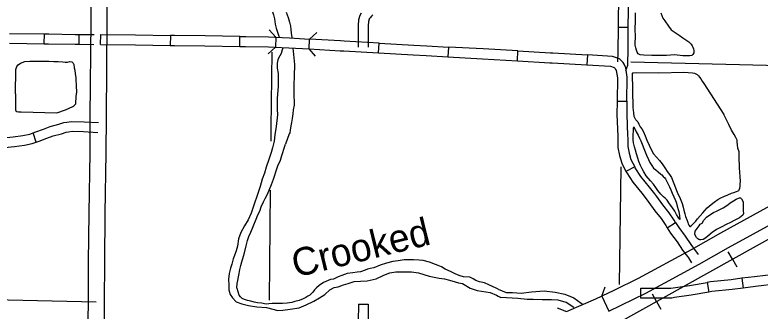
# Model space of a CAD drawing. Extents: x 1196286 to 1268366, y 2040822 to 2082115.
# Drawn here: x 1227299 to 1231542, y 2058115 to 2059803 of the extents above; entities that cross this region are included whole.
import ezdxf

# ---------------------------------------------------------------- set-up
doc = ezdxf.new("R2010")
doc.units = 0
for name, color, linetype in [('60', 7, 'Continuous'), ('61', 7, 'Continuous'), ('62', 7, 'Continuous'), ('G-ANNO-SYMB', 7, 'Continuous'), ('Level 69', 7, 'Continuous'), ('Level 71', 7, 'Continuous'), ('Level 72', 7, 'Continuous'), ('Level 76', 7, 'Continuous'), ('Level 81', 7, 'Continuous'), ('Level 83', 7, 'Continuous'), ('Level 84', 7, 'Continuous'), ('Level 87', 7, 'Continuous')]:
    doc.layers.add(name, color=color, linetype=linetype)

msp = doc.modelspace()

# ---------------------------------------------------------------- linework, layer by layer
at = {"layer": '60'}
for points in [[(1228761.5, 2059591.7), (1228756.7, 2059158.4)], [(1233094.3, 2059466.8), (1232738.1, 2059486.8), (1230806.4, 2059534.5)], [(1228756.7, 2059158.4), (1228756, 2059084.4)], [(1230749.7, 2058938.2), (1230739.2, 2058266.7)], [(1228753.1, 2058804.5), (1228746.7, 2058177.5)]]:
    msp.add_lwpolyline(points, dxfattribs=at)
at = {"layer": '61'}
for p, q in [((1227466.4, 2059638.8), (1227467.2, 2059695)), ((1230733.3, 2059733.9), (1230789.6, 2059733.2)), ((1227664.4, 2059635.9), (1227665.2, 2059692.2)), ((1231438.6, 2058302), (1231446, 2058246.2)), ((1231241, 2058278.9), (1231250.4, 2058223.4)), ((1230862.3, 2058189.6), (1230862.2, 2058245.9)), ((1229254.9, 2058155.2), (1229311.1, 2058154.3))]:
    msp.add_line(p, q, dxfattribs=at)
for points in [[(1230735.7, 2059931.9), (1230733.3, 2059733.9)], [(1230792, 2059931.2), (1230789.6, 2059733.2)], [(1227269.3, 2059697.9), (1227467.2, 2059695)], [(1227467.2, 2059695), (1227491.7, 2059694.7), (1227642.6, 2059692.5), (1227665.2, 2059692.2)], [(1230733.3, 2059733.9), (1230731.6, 2059595.4), (1230730.8, 2059535.9)], [(1230789.6, 2059733.2), (1230787.9, 2059594.6), (1230787.1, 2059535.2)], [(1227665.2, 2059692.2), (1227750.3, 2059691)], [(1227268.5, 2059641.6), (1227466.4, 2059638.8)], [(1227466.4, 2059638.8), (1227490.8, 2059638.4), (1227641.8, 2059636.3), (1227664.4, 2059635.9)], [(1227664.4, 2059635.9), (1227749.5, 2059634.7)], [(1230787.1, 2059535.2), (1230786.8, 2059514.3), (1230776.1, 2059484.6)], [(1231438.6, 2058302), (1231376.2, 2058293.7), (1231259.8, 2058282.1), (1231241, 2058278.9)], [(1231635.6, 2058326.2), (1231509.2, 2058311.4), (1231438.6, 2058302)], [(1231046, 2058247.7), (1231139.8, 2058261.8), (1231241, 2058278.9)], [(1231642.1, 2058270.4), (1231516.2, 2058255.5), (1231446, 2058246.2)], [(1230862.2, 2058245.9), (1231034.4, 2058246), (1231046, 2058247.7)], [(1231250.4, 2058223.4), (1231148.6, 2058206.3), (1231054.4, 2058192.1)], [(1231446, 2058246.2), (1231382.7, 2058237.8), (1231267.3, 2058226.3), (1231250.4, 2058223.4)], [(1231054.4, 2058192.1), (1231038.6, 2058189.7), (1230862.3, 2058189.6)], [(1229254.9, 2058155.2), (1229251.6, 2057957.3)], [(1229311.1, 2058154.3), (1229307.8, 2057956.3)]]:
    msp.add_lwpolyline(points, dxfattribs=at)
at = {"layer": '62'}
for points in [[(1228766.8, 2059820.7), (1228771.5, 2059802.9), (1228777.9, 2059780.8), (1228780.7, 2059750.7), (1228786.7, 2059727.9), (1228798.4, 2059692.9), (1228802.1, 2059681.9), (1228803.3, 2059678.4)], [(1228844.3, 2059818.9), (1228855.3, 2059789.3), (1228863.1, 2059761.2), (1228867.6, 2059739.6), (1228870.7, 2059719.9), (1228872.3, 2059699.6), (1228876.3, 2059674.7)], [(1230977.2, 2059814.8), (1230987.1, 2059784.8), (1230999, 2059769.7), (1231019.4, 2059739.7), (1231036, 2059718.1), (1231036.3, 2059718.5), (1231081.1, 2059687.7), (1231102.3, 2059673.5), (1231119.9, 2059660.5), (1231136, 2059649.5), (1231144, 2059641.7), (1231149.1, 2059635.9), (1231154.8, 2059626.7), (1231157.9, 2059618.7), (1231162.5, 2059609.5), (1231164.8, 2059598.9), (1231165, 2059593.2), (1231164, 2059587.6), (1231158.8, 2059577.3), (1231152.7, 2059572.2), (1231141.8, 2059570.3), (1231123, 2059569.4), (1231101.3, 2059570.1), (1231054.3, 2059575.4), (1231009.6, 2059572.3), (1230963.9, 2059572.3), (1230925.3, 2059572), (1230880.8, 2059573.1), (1230859.5, 2059576.4), (1230851, 2059578.9), (1230848.1, 2059581.3), (1230841.6, 2059590.5), (1230839, 2059601.5), (1230833.8, 2059616.3), (1230831.3, 2059631.5), (1230831.2, 2059650.3), (1230831.8, 2059670.9), (1230831.7, 2059689), (1230829.9, 2059713), (1230833, 2059779.3)], [(1230833, 2059779.3), (1230832.3, 2059814.6)], [(1228824.1, 2059614.2), (1228821.8, 2059604.6), (1228815.9, 2059584.1), (1228808.3, 2059569.6), (1228799.7, 2059557.1), (1228795.6, 2059548.2), (1228791.6, 2059528.1), (1228793.3, 2059499), (1228797.2, 2059468.8), (1228798.5, 2059437.2), (1228798.3, 2059397.3), (1228792.8, 2059327.6), (1228792.3, 2059267), (1228794.2, 2059233.9)], [(1228882.5, 2059611.4), (1228882.9, 2059595.8), (1228890.6, 2059520), (1228888.5, 2059453.8), (1228887, 2059405), (1228886.4, 2059375.3), (1228887.6, 2059353.1), (1228887, 2059335.8), (1228889.3, 2059313.5), (1228888.6, 2059289.1), (1228883.9, 2059261.4), (1228882.5, 2059240.1), (1228877.9, 2059212), (1228873.4, 2059190.3), (1228870.6, 2059171.2), (1228867.2, 2059147.3), (1228864.8, 2059131.9), (1228860.2, 2059125.7), (1228839.4, 2059067)], [(1227303, 2059353), (1227304.2, 2059492), (1227310, 2059508.7), (1227318.9, 2059519.7), (1227331.2, 2059528.3), (1227355.5, 2059537.7), (1227385.1, 2059539), (1227438.7, 2059539.5), (1227467.9, 2059540.4), (1227491.9, 2059540.1), (1227520.7, 2059538.7), (1227546.1, 2059538.3), (1227572.6, 2059535.9), (1227585.3, 2059534.4), (1227598.1, 2059534.4), (1227611.3, 2059537.3), (1227623.6, 2059535.8), (1227631.2, 2059528), (1227634.3, 2059520.8), (1227637.5, 2059502.3), (1227639.7, 2059489), (1227642.4, 2059468.3), (1227645.5, 2059447.1), (1227647.2, 2059432), (1227647.5, 2059405.3), (1227649.6, 2059357.6)], [(1230833.5, 2059205.6), (1230825.6, 2059224), (1230822, 2059244.4), (1230819, 2059275.8), (1230816, 2059471.6), (1230816.3, 2059473.6), (1230821.3, 2059473.8), (1230840.6, 2059475.4), (1230965.5, 2059473.3), (1231106.7, 2059476.9), (1231156, 2059473.2), (1231167.7, 2059470.4), (1231175.7, 2059467), (1231184.4, 2059463), (1231191.2, 2059456.8), (1231197.7, 2059448.9), (1231203.5, 2059439.9), (1231212.5, 2059425.5), (1231221.2, 2059412.7), (1231297.5, 2059295.2), (1231336.2, 2059236.3)], [(1227303, 2059353), (1227302.5, 2059262.4), (1227305.1, 2059255.9), (1227311, 2059252.8), (1227319.6, 2059251.6), (1227334.6, 2059250.3), (1227537.9, 2059245.6), (1227587.2, 2059261.4), (1227629.4, 2059280.4), (1227635.8, 2059284.4), (1227641.5, 2059290), (1227645.4, 2059296.7), (1227646.3, 2059306.1), (1227649.6, 2059357.6)], [(1228794.2, 2059233.9), (1228787.7, 2059167.8), (1228779.8, 2059119.7), (1228776.3, 2059082.9), (1228766.5, 2059046.5), (1228758.6, 2059019.2), (1228744.6, 2058978.8), (1228729.4, 2058935.4), (1228719.5, 2058900.9), (1228707.8, 2058867.2), (1228696.4, 2058825.6), (1228682.4, 2058785.2), (1228657.4, 2058713.7), (1228643.8, 2058673.7), (1228626.8, 2058636), (1228606.9, 2058602), (1228586.1, 2058563.2), (1228572.9, 2058528), (1228566.7, 2058485.6), (1228559.6, 2058458.6), (1228549.9, 2058432.8), (1228542.5, 2058412.2), (1228534.6, 2058383.4), (1228527.5, 2058359.8), (1228519.3, 2058329.8), (1228514.7, 2058297.2), (1228516.5, 2058263.3), (1228516.5, 2058237), (1228525.5, 2058209.4), (1228538.4, 2058190.4), (1228559.4, 2058168.3), (1228592.2, 2058156.6), (1228628.8, 2058146.3), (1228677, 2058138.9), (1228730.9, 2058135.1), (1228795.8, 2058118), (1228825.1, 2058121.4), (1228867.1, 2058126.1), (1228917.4, 2058133.3), (1228958.1, 2058150.4), (1229000.4, 2058172.7), (1229033.2, 2058190.3), (1229063.4, 2058209.9), (1229092.6, 2058236.1), (1229116.8, 2058249.3), (1229140.1, 2058254.3), (1229169.4, 2058264), (1229197.3, 2058273.1), (1229230.7, 2058283.1), (1229266.7, 2058284.9), (1229305, 2058287.4), (1229356.4, 2058299.8), (1229399.8, 2058319.1), (1229434.4, 2058332.9), (1229468.2, 2058338.5), (1229509.8, 2058339.4), (1229556.6, 2058339.1), (1229596.6, 2058333), (1229626.8, 2058324.6), (1229658.2, 2058314.8), (1229685.4, 2058308), (1229715, 2058302.7), (1229744.9, 2058299.3), (1229774.4, 2058290.6), (1229805.7, 2058281.2), (1229825.1, 2058276), (1229847.9, 2058271.9), (1229890.6, 2058245.4), (1229930.1, 2058232.1), (1229981.3, 2058224.2), (1230004.9, 2058220.5), (1230041.8, 2058205.3), (1230050.7, 2058199.9), (1230066, 2058192.5)], [(1230833.5, 2059205.6), (1230845.8, 2059193.7), (1230851.4, 2059181.3), (1230859.8, 2059165.8), (1230868.1, 2059154.3), (1230877.7, 2059137.8), (1230888.2, 2059113.5), (1230897.6, 2059089.2), (1230909.7, 2059060.8), (1230922.8, 2059032.8), (1230935.5, 2059012.3), (1230951.7, 2058993.4), (1230968.6, 2058973.7), (1230984.1, 2058954), (1231002.7, 2058926.6), (1231013.2, 2058910.3), (1231026.4, 2058894), (1231036.9, 2058876.2), (1231059.2, 2058818.5), (1231069.8, 2058793.4), (1231086.6, 2058757.4), (1231098.6, 2058727.9), (1231104, 2058707.2), (1231107.6, 2058691.1), (1231112.8, 2058669), (1231116.7, 2058655), (1231125.8, 2058631.7), (1231129.7, 2058621.1), (1231132.5, 2058611.7), (1231135.5, 2058605.8), (1231140.8, 2058597.5), (1231141.2, 2058597), (1231141.7, 2058596.9), (1231143.1, 2058597.3), (1231149.3, 2058601.9), (1231155.5, 2058607.6), (1231165.6, 2058618.2), (1231175.1, 2058628.1), (1231186.2, 2058641.1), (1231201.3, 2058658.6), (1231216.4, 2058674.7), (1231226.4, 2058688.1), (1231240.7, 2058704.6), (1231262.5, 2058722.7), (1231279.9, 2058736.2), (1231301.2, 2058750.8), (1231317.4, 2058761.2), (1231334.9, 2058768.6), (1231357.2, 2058777.4), (1231378.7, 2058786.4), (1231391.9, 2058792), (1231407.3, 2058797.7), (1231416.9, 2058801), (1231420.2, 2058803.4), (1231422.3, 2058806.3), (1231425.7, 2058815.4), (1231427.8, 2058824.5), (1231428.6, 2058838.4), (1231429.6, 2058856.1), (1231424.3, 2058931.4), (1231421.7, 2058993.6), (1231421.8, 2059022.4), (1231414.7, 2059043.7), (1231412.2, 2059063.1), (1231411.7, 2059079.5), (1231410.3, 2059090.3), (1231403.8, 2059104.7), (1231393.6, 2059121.6), (1231379.4, 2059146.9), (1231363.3, 2059177.9), (1231336.2, 2059236.3)], [(1231083.9, 2058637.3), (1231075.7, 2058650.5), (1231065.9, 2058666.7), (1231055.9, 2058683.9), (1231038.4, 2058708.9), (1231026.7, 2058726.3), (1231012, 2058747.8), (1231000.9, 2058759.2), (1230991.6, 2058767.3), (1230976.2, 2058782.4), (1230960.5, 2058801.9), (1230948.5, 2058819.6), (1230934.6, 2058839), (1230918.2, 2058857.9), (1230893.5, 2058886.7), (1230880, 2058908.3), (1230870.3, 2058926.2), (1230860.7, 2058945.1), (1230851.5, 2058968.7), (1230845.5, 2058987.3), (1230838.4, 2059011), (1230831.5, 2059032.1), (1230825.9, 2059051.8), (1230821.1, 2059074.2), (1230818.5, 2059091.6), (1230818.3, 2059102.2), (1230820, 2059121.1), (1230821, 2059140.2), (1230821.3, 2059156.6), (1230822, 2059166), (1230823.4, 2059162.6), (1230830.1, 2059149.9), (1230836.7, 2059136.9), (1230842.2, 2059127.1), (1230846.9, 2059117.7), (1230855.6, 2059101.6), (1230862.7, 2059085.8), (1230870.2, 2059066.3), (1230880, 2059041.2), (1230895.7, 2059004.8), (1230906.2, 2058979.7), (1230914.1, 2058962.2), (1230924.5, 2058945), (1230935.6, 2058930.7), (1230948.3, 2058919.6), (1230960.8, 2058908.3), (1230976.6, 2058896.5), (1230982, 2058891.3), (1230989.4, 2058883.2), (1230998.5, 2058874.6), (1231003.7, 2058868.3), (1231009.7, 2058858.2), (1231016.9, 2058842.1), (1231026.7, 2058823.6), (1231034.2, 2058805.9), (1231041.4, 2058787.4), (1231050.6, 2058765.9), (1231060.4, 2058745.9), (1231064.4, 2058735.7), (1231067.9, 2058722.3), (1231070, 2058713.4), (1231076.1, 2058693.6), (1231078.5, 2058682), (1231080.8, 2058669), (1231082.1, 2058659.3), (1231083.9, 2058637.3)], [(1228994.7, 2058222.5), (1228990.5, 2058216.5), (1228978.3, 2058206.9), (1228967, 2058199.5), (1228955.7, 2058193.3), (1228940.2, 2058184.5), (1228917.6, 2058175), (1228893.6, 2058170.8), (1228875.5, 2058163.9), (1228848.5, 2058160.9), (1228823.4, 2058158.3), (1228799.8, 2058159), (1228764.5, 2058158.3), (1228745.4, 2058156.7), (1228729.7, 2058155.1), (1228703.1, 2058159.9), (1228679.6, 2058162.5), (1228661.6, 2058165.8), (1228641.9, 2058171.7), (1228624.3, 2058175.3), (1228607.1, 2058180.4), (1228593.4, 2058187.4), (1228584.1, 2058196.9), (1228576.4, 2058206.4), (1228564.2, 2058244.2), (1228563.1, 2058248.4), (1228564.6, 2058272), (1228567.8, 2058290), (1228572.6, 2058311.4), (1228576.2, 2058328.7), (1228579.5, 2058351.6), (1228585.1, 2058375.6), (1228592.1, 2058395.4), (1228600, 2058428), (1228606.3, 2058448.2), (1228615.4, 2058487.2), (1228623.7, 2058516.8), (1228631.5, 2058540.4), (1228642.7, 2058564.3), (1228672.9, 2058639.4), (1228682.6, 2058663), (1228693, 2058685), (1228701.6, 2058708.6), (1228715.1, 2058737), (1228724.7, 2058756.8), (1228734.7, 2058778.1), (1228747.1, 2058803.5), (1228761, 2058837.2), (1228771.9, 2058866.3), (1228779.3, 2058889.2), (1228785.2, 2058909.8), (1228796.5, 2058942.3), (1228810.8, 2058975.2), (1228819, 2059001.8), (1228825.3, 2059019.4), (1228830.4, 2059037.8), (1228839.4, 2059067)], [(1231201.5, 2058610.1), (1231211.3, 2058617.3), (1231222, 2058632.6), (1231237.2, 2058650.4), (1231250.1, 2058660.8), (1231276.9, 2058677.3), (1231293.1, 2058685.4), (1231312.4, 2058694.5), (1231332.4, 2058704.7), (1231358, 2058721.3), (1231371.3, 2058731.7), (1231390.9, 2058743.4), (1231405.7, 2058752.2), (1231418.1, 2058759.6), (1231425.3, 2058761.4), (1231430.9, 2058759.8), (1231436.4, 2058754.1), (1231444.1, 2058741.9), (1231445.5, 2058735.7)], [(1231445.5, 2058735.7), (1231445.2, 2058724.7), (1231445.7, 2058704.8), (1231446.2, 2058687.1), (1231446.4, 2058672.4), (1231442.9, 2058661.9), (1231423.6, 2058646.4), (1231397.6, 2058633.6), (1231373.8, 2058620.8), (1231349.3, 2058608.7), (1231324.8, 2058596.2), (1231293.8, 2058580.5), (1231269.6, 2058563.9), (1231244.2, 2058542.8), (1231232.5, 2058532.8), (1231218.5, 2058523.6), (1231204.2, 2058520.8), (1231199.4, 2058520.9), (1231193, 2058523.2), (1231187.1, 2058527.5), (1231180.1, 2058533.9), (1231172.4, 2058547.2)], [(1231172.4, 2058547.2), (1231169.3, 2058553.4), (1231171.4, 2058571), (1231182.8, 2058586.3), (1231194.6, 2058601.5), (1231201.5, 2058610.1)], [(1230049.8, 2058240.9), (1230039, 2058246.7), (1229997.3, 2058265.7), (1229972.7, 2058277), (1229945.1, 2058282.6), (1229923.8, 2058289.3), (1229908.9, 2058299.3), (1229890, 2058308.2), (1229852.5, 2058310.2), (1229833.9, 2058316.9), (1229809.7, 2058325.5), (1229778.4, 2058340.2), (1229749, 2058354.9), (1229728.6, 2058366.8), (1229708.5, 2058375.8), (1229693.9, 2058380.9), (1229660, 2058393.7), (1229623.4, 2058403.7), (1229600.6, 2058405.8), (1229568, 2058406.7), (1229515.6, 2058406.7), (1229481.4, 2058402.2), (1229450.3, 2058397), (1229415.3, 2058389.2), (1229378.1, 2058376.6), (1229342.3, 2058362.4), (1229322, 2058357.8), (1229307.3, 2058353.9), (1229292.7, 2058348.8), (1229266.7, 2058339.8), (1229248.3, 2058336.3), (1229222.4, 2058332.9), (1229191.6, 2058329.5), (1229160.4, 2058317.6), (1229140.1, 2058309.9), (1229112.9, 2058297.9), (1229096, 2058294.4), (1229055.7, 2058278), (1229031.1, 2058261.1), (1229016, 2058247.7), (1229004.2, 2058236.2), (1228994.7, 2058222.5)], [(1230049.8, 2058240.9), (1230096.9, 2058221.7), (1230132.7, 2058222.1), (1230182.1, 2058218.1), (1230240.1, 2058225.2), (1230311.8, 2058229.9), (1230375, 2058223.3), (1230430.2, 2058211.3), (1230480.9, 2058189.9), (1230523.3, 2058161.1), (1230533.9, 2058152.7)], [(1230480.6, 2058135.9), (1230438.1, 2058164.7), (1230393, 2058178.2), (1230353.3, 2058179.9), (1230301.7, 2058180.2), (1230250.1, 2058180.5), (1230216.4, 2058181.9), (1230162.9, 2058186.1), (1230066, 2058192.5)]]:
    msp.add_lwpolyline(points, dxfattribs=at)
at = {"layer": 'G-ANNO-SYMB'}
msp.add_lwpolyline([(1226394, 2058199.1), (1226761.3, 2058189.9), (1226894.2, 2058186.5), (1227012.2, 2058184.9), (1227260.5, 2058179.6), (1227762.7, 2058168.8)], dxfattribs=at)
at = {"layer": 'Level 69'}
msp.add_line((1227420.1, 2059077.2), (1227402.9, 2059130.7), dxfattribs=at)
for points in [[(1227402.9, 2059130.7), (1227419.1, 2059136), (1227461.6, 2059152.7), (1227501, 2059167.9), (1227548.7, 2059179.9), (1227577.7, 2059189.3), (1227595.2, 2059192)], [(1227595.2, 2059192), (1227621.6, 2059196.3), (1227693, 2059194.1), (1227774.4, 2059189.9)], [(1227212.8, 2059099.9), (1227235.2, 2059102.8), (1227290.1, 2059108.8), (1227343.7, 2059116.9), (1227383.5, 2059124.5), (1227402.9, 2059130.7)], [(1227420.1, 2059077.2), (1227438, 2059083), (1227482.1, 2059100.3), (1227518, 2059114.2), (1227564.2, 2059125.8), (1227590.9, 2059134.4), (1227604, 2059136.5)], [(1227604, 2059136.5), (1227625.2, 2059139.9), (1227690.7, 2059137.9), (1227771.5, 2059133.8)], [(1227220.1, 2059044.1), (1227241.9, 2059046.9), (1227297.3, 2059053), (1227353.2, 2059061.4), (1227397.5, 2059069.9), (1227420.1, 2059077.2)]]:
    msp.add_lwpolyline(points, dxfattribs=at)
at = {"layer": 'Level 71'}
for p, q in [((1227787.6, 2059635.5), (1227788.4, 2059691.8)), ((1228184.3, 2059686.1), (1228183.5, 2059629.9)), ((1228579.5, 2059624.2), (1228580.3, 2059680.5)), ((1228580.3, 2059680.5), (1228580.3, 2059680.5)), ((1228973.9, 2059609.5), (1228977.1, 2059665.6)), ((1229369.3, 2059586.9), (1229372.5, 2059643)), ((1229767.9, 2059620.4), (1229764.7, 2059564.3)), ((1229369.3, 2059586.9), (1229369.3, 2059586.9)), ((1230160, 2059541.7), (1230163.2, 2059597.9)), ((1230558.6, 2059575.3), (1230555.4, 2059519.1)), ((1230767.2, 2059522.7), (1230767.2, 2059522.7)), ((1230727.4, 2059312.5), (1230783.6, 2059311.6)), ((1230827.7, 2058937), (1230777.8, 2058911.2)), ((1231013, 2058590), (1231060.2, 2058620.5))]:
    msp.add_line(p, q, dxfattribs=at)
for points in [[(1227788.4, 2059691.8), (1227986.4, 2059689)], [(1227986.4, 2059689), (1228184.3, 2059686.1)], [(1228382.3, 2059683.3), (1228208.2, 2059685.8), (1228184.3, 2059686.1)], [(1228580.3, 2059680.5), (1228382.3, 2059683.3)], [(1228580.3, 2059680.5), (1228613.9, 2059680), (1228744, 2059678.1), (1228779.2, 2059676.3)], [(1228779.2, 2059676.3), (1228862.3, 2059672.2), (1228977.1, 2059665.6)], [(1228785.3, 2059676), (1228782.5, 2059619.9)], [(1229174.8, 2059654.3), (1229153.5, 2059655.5), (1228977.1, 2059665.6)], [(1229372.5, 2059643), (1229174.8, 2059654.3)], [(1227787.6, 2059635.5), (1227985.6, 2059632.7)], [(1227985.6, 2059632.7), (1228183.5, 2059629.9)], [(1228183.5, 2059629.9), (1228207.4, 2059629.5), (1228381.5, 2059627)], [(1228381.5, 2059627), (1228579.5, 2059624.2)], [(1228579.5, 2059624.2), (1228613.1, 2059623.7), (1228742.2, 2059621.9), (1228776.4, 2059620.2)], [(1228776.4, 2059620.2), (1228859.3, 2059616), (1228973.9, 2059609.5)], [(1228973.9, 2059609.5), (1229150.3, 2059599.4), (1229171.6, 2059598.2)], [(1229372.5, 2059643), (1229570.2, 2059631.7)], [(1229570.2, 2059631.7), (1229644.1, 2059627.5), (1229767.9, 2059620.4)], [(1229965.5, 2059609.1), (1229767.9, 2059620.4)], [(1230163.2, 2059597.9), (1229965.5, 2059609.1)], [(1229171.6, 2059598.2), (1229369.3, 2059586.9)], [(1229369.3, 2059586.9), (1229567, 2059575.6)], [(1229567, 2059575.6), (1229640.9, 2059571.4), (1229764.7, 2059564.3)], [(1230163.2, 2059597.9), (1230348.3, 2059587.3), (1230360.9, 2059586.6)], [(1230360.9, 2059586.6), (1230558.6, 2059575.3)], [(1230767.2, 2059522.7), (1230761.6, 2059531.8), (1230742, 2059552.2), (1230701.4, 2059567.1), (1230558.6, 2059575.3)], [(1229764.7, 2059564.3), (1229962.3, 2059553)], [(1229962.3, 2059553), (1230160, 2059541.7)], [(1230160, 2059541.7), (1230345.1, 2059531.1), (1230357.7, 2059530.4)], [(1230357.7, 2059530.4), (1230555.4, 2059519.1)], [(1230555.4, 2059519.1), (1230689.9, 2059511.4), (1230710.4, 2059503.9), (1230716.9, 2059497.1), (1230719.4, 2059493.1)], [(1230719.4, 2059493.1), (1230719.9, 2059492.3), (1230722.6, 2059485.9), (1230729.4, 2059443.8), (1230727.4, 2059312.5)], [(1230783.6, 2059311.6), (1230785.8, 2059447.9), (1230777, 2059501.7), (1230770, 2059518.3), (1230767.2, 2059522.7)], [(1230727.4, 2059312.5), (1230726.2, 2059235.7), (1230731.6, 2059112.9)], [(1230783.6, 2059311.6), (1230782.5, 2059236.5), (1230787.8, 2059115.4)], [(1230731.6, 2059112.9), (1230732.2, 2059099.5), (1230732.3, 2059047), (1230741.1, 2059001.3), (1230753.7, 2058957.8), (1230777.8, 2058911.2)], [(1230787.8, 2059115.4), (1230788.5, 2059100.8), (1230788.5, 2059052.4), (1230795.9, 2059014.5), (1230806.2, 2058978.7), (1230827.7, 2058937)], [(1230942.8, 2058782.6), (1230912, 2058822.2), (1230862.3, 2058882.5), (1230830.9, 2058930.9), (1230827.7, 2058937)], [(1230777.8, 2058911.2), (1230782.2, 2058902.6), (1230816.9, 2058849.2), (1230868.1, 2058787.1), (1230898.3, 2058748.1)], [(1231060.2, 2058620.5), (1231051.7, 2058633.7), (1231024.8, 2058676.1), (1230987.5, 2058720.7), (1230954.3, 2058767.8), (1230942.8, 2058782.6)], [(1230898.3, 2058748.1), (1230909.1, 2058734.3), (1230942.8, 2058686.4), (1230979.2, 2058642.8), (1231004.4, 2058603.3), (1231013, 2058590)], [(1231060.2, 2058620.5), (1231078.6, 2058592.1), (1231115.4, 2058543.1), (1231146.6, 2058495.7), (1231173, 2058460.3)], [(1231013, 2058590), (1231032.5, 2058559.9), (1231069.3, 2058510.8), (1231100.5, 2058463.3), (1231128, 2058426.6)], [(1231128, 2058426.6), (1231134.3, 2058418.2), (1231151.7, 2058391.1)], [(1231173, 2058460.3), (1231180.5, 2058450.3), (1231189.2, 2058436.9)]]:
    msp.add_lwpolyline(points, dxfattribs=at)
at = {"layer": 'Level 72'}
for points in [[(1229269.8, 2059813.9), (1229262.7, 2059800.2), (1229256.1, 2059775.8), (1229254.2, 2059743.1), (1229254.3, 2059711.2), (1229253.6, 2059620.3)], [(1229336.6, 2059803.7), (1229328.7, 2059796), (1229321.8, 2059787.4), (1229316.4, 2059781.5), (1229315.5, 2059779.7), (1229311.9, 2059766.7), (1229310.5, 2059741.6), (1229310.6, 2059711.1), (1229309.9, 2059619.8)]]:
    msp.add_lwpolyline(points, dxfattribs=at)
at = {"layer": 'Level 76'}
for points in [[(1230640.2, 2058199.9), (1230659.3, 2058252.8)], [(1230387.2, 2058132.9), (1230439.4, 2058112.1)]]:
    msp.add_lwpolyline(points, dxfattribs=at)
at = {"layer": 'Level 81'}
for p, q in [((1231384.9, 2058410.3), (1231360.8, 2058453.5)), ((1231384.9, 2058410.3), (1231409, 2058367.1)), ((1230952.5, 2058169.2), (1230928.4, 2058212.5)), ((1230952.5, 2058169.2), (1230976.6, 2058126))]:
    msp.add_line(p, q, dxfattribs=at)
for points in [[(1235621.7, 2060865.7), (1235429, 2060684.3), (1235383.9, 2060644.8), (1235336.1, 2060612.8), (1235294.3, 2060583), (1235226.8, 2060546), (1234565.1, 2060170.6), (1234169.8, 2059954.7), (1233639.8, 2059656.3), (1232843.5, 2059217.9), (1231651.7, 2058559.1), (1230722.4, 2058040.9)], [(1232843.5, 2059217.9), (1231651.7, 2058559.1), (1230722.4, 2058040.9), (1230500.2, 2057922.6), (1230464.3, 2057903.9), (1230407.8, 2057880.2), (1230370.2, 2057864.6), (1230342.3, 2057857.1), (1230311.2, 2057850), (1230256.3, 2057834.9), (1230170, 2057825.2), (1230023.6, 2057805.8), (1229812.4, 2057777.5), (1229032.6, 2057674.8), (1227877.5, 2057519.3), (1227224.9, 2057432.8), (1226438.4, 2057327.5), (1226182.7, 2057296.1)], [(1232843.5, 2059217.9), (1231651.7, 2058559.1), (1230722.4, 2058040.9), (1230500.2, 2057922.6), (1230464.3, 2057903.9), (1230407.8, 2057880.2), (1230370.2, 2057864.6), (1230342.3, 2057857.1), (1230311.2, 2057850), (1230256.3, 2057834.9), (1230170, 2057825.2), (1230023.6, 2057805.8), (1229812.4, 2057777.5), (1229032.6, 2057674.8), (1227877.5, 2057519.3), (1227224.9, 2057432.8), (1226438.4, 2057327.5), (1226182.7, 2057296.1)]]:
    msp.add_lwpolyline(points, dxfattribs=at)
at = {"layer": 'Level 83'}
for points in [[(1228747.6, 2059717.8), (1228785.3, 2059676)], [(1228977.1, 2059665.6), (1229019.1, 2059703.1)], [(1228782.5, 2059619.9), (1228740.8, 2059582.1)], [(1229011.4, 2059567.5), (1228973.9, 2059609.5)]]:
    msp.add_lwpolyline(points, dxfattribs=at)
at = {"layer": 'Level 84'}
for points in [[(1232747.3, 2059346.9), (1232270.6, 2059087), (1231763.6, 2058805.5), (1231315.9, 2058559.5), (1231149.2, 2058464.9), (1230848.1, 2058301.2), (1230709.5, 2058232.5), (1230640.2, 2058199.9)], [(1230680.2, 2058115.1), (1230750.3, 2058148.1), (1230891.3, 2058217.9), (1231194.8, 2058383), (1231361.6, 2058477.6), (1231808.9, 2058723.5), (1232315.8, 2059004.9), (1232792.2, 2059264.6)], [(1230640.2, 2058199.9), (1230605, 2058183.3), (1230437.1, 2058111)], [(1230640.2, 2058199.9), (1230680.2, 2058115.1)]]:
    msp.add_lwpolyline(points, dxfattribs=at)
at = {"layer": 'Level 87'}
for points in [[(1227809.2, 2058061.7), (1227809.5, 2058168.6), (1227810.7, 2058395.2), (1227814.1, 2058671.3), (1227819.2, 2059017.4), (1227820.1, 2059224.4), (1227825.4, 2059766.8), (1227827.2, 2060023.6), (1227840.6, 2060564.2), (1227865, 2061344.6), (1227868.4, 2061441.9), (1227867.3, 2061476.6), (1227861.8, 2061502.6), (1227853.8, 2061529.6), (1227843.6, 2061550.9), (1227830.3, 2061575.3), (1227810.8, 2061604.3), (1227786.5, 2061636.3), (1227753, 2061665.4), (1227721.4, 2061689.5), (1227677, 2061704.3), (1227558, 2061705.8), (1227415.4, 2061710.7), (1227378.2, 2061715.3)], [(1227733.5, 2060025.1), (1227731.7, 2059767.6), (1227726.3, 2059225.1), (1227725.4, 2059018.3), (1227720.4, 2058672.6), (1227717, 2058396), (1227715.8, 2058169), (1227715.4, 2058062)]]:
    msp.add_lwpolyline(points, dxfattribs=at)

# ---------------------------------------------------------------- texts
at = {"layer": '62'}
msp.add_text('Crooked', height=158.4, rotation=13.7949, dxfattribs=at).set_placement((1228897.3, 2058305.7))

doc.saveas('drawing.dxf')
